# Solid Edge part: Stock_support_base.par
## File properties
Title: Stock Support Base
Author: Abhinav Rai
Template: Normal.par
Last saved by: Rajat Kamboj
Revision: 25
Application: Solid Edge
Accuracy: 0.99
Material: aluminum
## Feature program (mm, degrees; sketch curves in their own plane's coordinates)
sketch for "unnamed RevolvedProtrusion 1" plane through (0, 0, 0) normal (0, -1, 0) x-axis (1, 0, 0)
  line (0, 29.2468) -> (71.7103, 29.2468)
  line (71.7103, 29.2468) -> (71.7103, 19.7218)
  line (71.7103, 19.7218) -> (165.1, -256.5032)
  line (165.1, -256.5032) -> (215.9, -256.5032)
  line (215.9, -256.5032) -> (215.9, -281.9032)
  line (215.9, -281.9032) -> (156.9298, -281.9032)
  line (156.9298, -281.9032) -> (85.052, -69.3053)
  arc centre (73.021, -73.3729) radius 12.7 from (60.325, -73.0538) to (85.052, -69.3053) cw
  line (60.325, -73.0538) -> (57.15, -199.3532)
  line (57.15, -199.3532) -> (0, -199.3532)
  line (0, 29.2468) -> (0, -199.3532)
revolve "unnamed RevolvedProtrusion 1" add full turn 360 deg
sketch for "unnamed Hole 1" plane through (0, 0, 29.2468) normal (0, 0, 1) x-axis (1, 0, 0)
  hole centre (0, 0) bore radius 38.1
hole "unnamed Hole 1" through
sketch for "ExtrudedProtrusion_2" plane through (0, 0, -256.5032) normal (0, 0, 1) x-axis (0, 1, 0)
  arc centre (0, -119.2664) radius 41.0756 from (-18.7686, -155.8034) to (18.7686, -155.8034) ccw
  line (-18.7686, -197.1314) -> (-18.7686, -155.8034)
  arc centre (0, -197.1314) radius 18.7686 from (18.7686, -197.1314) to (-18.7686, -197.1314) cw
  line (18.7686, -197.1314) -> (18.7686, -155.8034)
extrude "ExtrudedProtrusion_2" add finite 12.7 along +normal
sketch for "unnamed Hole 2" plane through (187.8036, 0, -243.8032) normal (0, 0, 1) x-axis (1, 0, 0)
hole "unnamed Hole 2" through
fillet "Round_4" radius 3.175
pattern "unnamed Pattern 1" of "ExtrudedProtrusion_2", "unnamed Hole 2", "Round_4"
pattern "unnamed Pattern 2"
sketch for "ExtrudedProtrusion_3" plane through (0, -134.62, 0) normal (0, -1, 0) x-axis (1, 0, 0)
  circle centre (0, -2.5032) radius 19.05
extrude "ExtrudedProtrusion_3" add  Plane_Distance = 134.62 mm
adv blend "unnamed AdvBlend 1"
sketch for "ExtrudedProtrusion_4" plane through (0, -134.62, -2.5032) normal (0, -1, 0) x-axis (1, 0, 0)
  circle centre (0, -3.81) radius 22.225
extrude "ExtrudedProtrusion_4" add finite 9.525 along +normal
mirror "unnamed Mirror 1" of "ExtrudedProtrusion_4", "unnamed AdvBlend 1", "ExtrudedProtrusion_3" about plane through (0, 0, 0) normal (0, -1, 0)
extrude "unnamed Protrusion 1" add
adv blend "unnamed AdvBlend 2"
extrude "unnamed Protrusion 2" add finite 9.525
sketch for "ExtrudedProtrusion_7" plane through (104.775, 0, 0) normal (1, 0, 0) x-axis (0, 1, 0)
  circle centre (0, -167.6032) radius 19.05
extrude "ExtrudedProtrusion_7" add finite 41.275 along +normal  Plane_Distance = 104.775 mm
sketch for "unnamed Hole 3" plane through (146.05, 0, -167.6032) normal (1, 0, 0) x-axis (0, 1, 0)
  hole centre (0, 0) bore radius 7.9375
hole "unnamed Hole 3" through
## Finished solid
Body 1: solid body, 54 faces, 95 edges, 41 vertices.
  Faces by surface: plane 26, cylinder 19, torus 4, cone 3, blend 2
  Edges by curve: circle 57, intersection 20, line 18
Bounding box of the edges (mm; curved faces can reach further): 431.800 x 431.800 x 311.150, from (-215.9, -215.9, -281.9032) to (215.9, 215.9, 29.2468).
Cylindrical faces by radius (mm): R7.9375 x1, R11.1125 x3, R15.875 x3, R18.7686 x3, R19.05 x4, R22.225 x2, R38.1 x1, R71.7103 x1, R215.9 x1
Conical faces (half-angle, radius in mm at the cone's reference point): 1.44 deg R60.325 x1, 18.68 deg R71.7103 x1, 18.68 deg R156.9298 x1
Toroidal faces (ring radius, tube radius in mm): R73.021 r12.7 x1, R163.0843 r3.175 x3
Planar faces by outward normal: +x 1, +y 4, +z 10, -x 1, -y 4, -z 2, oblique 4
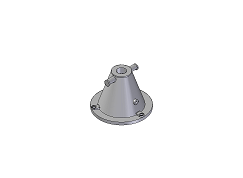
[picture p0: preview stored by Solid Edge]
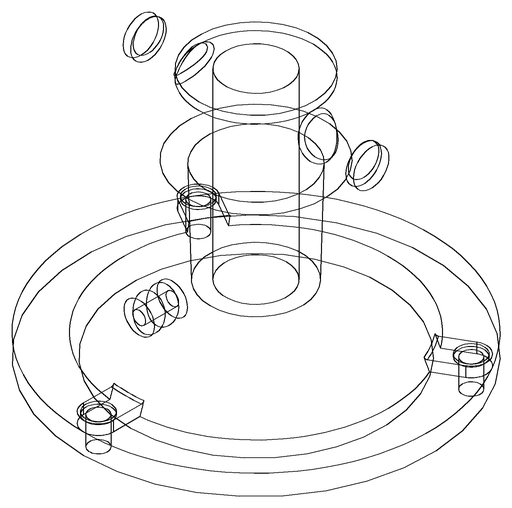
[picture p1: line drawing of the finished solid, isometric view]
